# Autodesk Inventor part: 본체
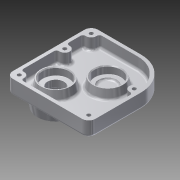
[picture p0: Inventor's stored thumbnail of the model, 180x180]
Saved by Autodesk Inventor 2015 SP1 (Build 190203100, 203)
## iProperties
Created: 2015-11
Part Number: 본체
Material: 알루미늄 6061
Document SubType Name: Modeling
Designer: moonsoo
Density: 2.7 g/cm^3
Appearance: 알루미늄 - 평지
Mass: 246.668 g
Surface Area: 389.43 cm^2
Volume: 91.3586 cm^3
Author: moonsoo
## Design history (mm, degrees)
sketch "스케치1"
  geometry: L1 (-42, 51.5)-(10, 51.5); L2 (50, 11.5)-(50, -43.5); L3 (42, -51.5)-(-42, -51.5); L4 (-50, -43.5)-(-50, 43.5); L5 (-50, 51.5)-(50, -51.5); L6 (50, 51.5)-(-50, -51.5); L7 (10, 47.5)-(-33.056, 47.5); L8 (-33.056, -47.5)-(33.056, -47.5); L9 (42, -43.5)-(42, 11.5); L10 (46, -34.556)-(46, 2.556); L11 (42, 11.5)-(-42, 11.5); L12 (-46, 34.556)-(-46, 20.444); L13 (-46, 2.556)-(-46, -34.556); L14 (-42, 43.5)-(-42, 11.5); A1 r 40 centre (10, 11.5) between (50, 11.5) and (10, 51.5); A2 r 8 centre (-42, 43.5) between (-42, 51.5) and (-50, 43.5); A3 r 8 centre (-42, -43.5) between (-50, -43.5) and (-42, -51.5); A4 r 8 centre (42, -43.5) between (42, -51.5) and (50, -43.5); A5 r 36 centre (10, 11.5) between (44.636, 21.314) and (10, 47.5); A6 r 6 centre (-42, 43.5) between (-42.667, 37.537) and (-36.037, 44.167); A7 r 3 centre (-33.056, 44.5) between (-33.056, 47.5) and (-36.037, 44.167); A8 r 3 centre (-43, 34.556) between (-42.667, 37.537) and (-46, 34.556); A9 r 6 centre (42, -43.5) between (42.667, -37.537) and (36.037, -44.167); A10 r 3 centre (43, -34.556) between (42.667, -37.537) and (46, -34.556); A11 r 3 centre (33.056, -44.5) between (33.056, -47.5) and (36.037, -44.167); A12 r 6 centre (42, 11.5) between (41.833, 17.498) and (42.667, 5.537); A13 r 3 centre (41.75, 20.497) between (41.833, 17.498) and (44.636, 21.314); A14 r 3 centre (43, 2.556) between (46, 2.556) and (42.667, 5.537); A15 r 6 centre (-42, 11.5) between (-42.667, 5.537) and (-42.667, 17.463); A16 r 3 centre (-43, 20.444) between (-46, 20.444) and (-42.667, 17.463); A17 r 3 centre (-43, 2.556) between (-42.667, 5.537) and (-46, 2.556); A18 r 6 centre (-42, -43.5) between (-36.037, -44.167) and (-42.667, -37.537); A19 r 3 centre (-43, -34.556) between (-46, -34.556) and (-42.667, -37.537); A20 r 3 centre (-33.056, -44.5) between (-36.037, -44.167) and (-33.056, -47.5); 10 further points
  constraints: 49 point on circle, 29 end point, 29 tangent, 20 centre point, 15 point on line, 7 equal radius, 5 coincident, 5 parallel, 5 perpendicular, 2 midpoint, 1 horizontal
  dimensions: "d0" = 100 distance of L5.end L6.end; "d1" = 103 distance of L6.start L5.end; "d2" = 40 radius of A1; "d3" = 8 radius of A2; "d4" = 4 distance between parallel lines of L7 L1; "d6" = 6 radius of A6; "d7" = 3 radius of A7; "d8" = 6 radius of A9; "d9" = 3 radius of A10; "d11" = 6 radius of A12; "d12" = 3 radius of A13; "d13" = 6 radius of A15; "d14" = 3 radius of A16; "d15" = 6 radius of A18; "d16" = 3 radius of A19; "d17" = 63 distance from line of L11.end L3; "d18" = 84 distance from line of A2.centre L9; "d19" = 4 distance between parallel lines of L2 L10; "d20" = 4 distance between parallel lines of L3 L8; "d21" = 4 distance between parallel lines of L13 L4; "d22" = 3 radius of A17 (derived)
extrude "돌출1" new body sketch "스케치1" distance "d23" = 18; taper "d24" = 0 deg
extrude "돌출2" join sketch "스케치1" distance "d25" = 4; taper "d26" = 0 deg
sketch "스케치2"
  geometry: A1 r 8 centre (-42, -43.5) between (-50, -43.5) and (-42, -51.5) reference; A2 r 8 centre (42, -43.5) between (42, -51.5) and (50, -43.5) reference; A3 r 6 centre (42, 43.5) between (36.037, 44.167) and (42.667, 37.537) reference; 6 further points
  constraints: 3 coincident
hole "구멍2" sketch "스케치2" at (-42, -43.5), (42, 11.5), (42, 43.5), (42, -43.5), (-42, 11.5) diameter "d34" = 4.5; stored, may be unused: countersink angle "d38" = 90 deg, drill point angle "d40" = 118 deg; dims "d35" = 6, "d36" = 8, "d37" = 4.4, "d39" = 8
sketch "스케치3"
  geometry: L1 (-42, -51.5)-(42, -51.5) reference; L2 (-42, 11.5)-(42, 11.5); L3 (-50, 43.5)-(-50, -43.5) reference; L4 (10, 43.5)-(10, -43.5); C1 r 2.25 at (42, -43.5) reference; C2 r 20 at (10, 11.5); A1 r 36 centre (10, 11.5) between (44.636, 21.314) and (10, 47.5) reference; 1 further point
  constraints: 4 end point, 2 parallel, 1 centre point, 1 coincident
  dimensions: "d42" = 63 distance between parallel lines of L1 L2; "d43" = 60 distance between parallel lines of L3 L4; "d44" = 40 diameter of C2
extrude "돌출3" join sketch "스케치3" distance "d45" = 11; taper "d46" = -10 deg
hole "구멍3" diameter "d49" = 22; stored, may be unused: countersink angle "d53" = 90 deg, drill point angle "d55" = 0 deg; dims "d50" = 6, "d51" = 32, "d52" = 9, "d54" = 11, "d60" = 10, "d61" = 10
chamfer "모따기1" distance "d56" = 1; stored, may be unused: second distance "d57" = 2, angle "d58" = 45 deg
fillet "모깎기1" dims "d59" = 3
fillet "모깎기2" dims "d62" = 0.3
sketch "스케치4"
  geometry: L1 (-42, -51.5)-(42, -51.5) reference; L2 (-50, -21.5)-(42, -21.5); L3 (-50, 43.5)-(-50, -43.5) reference; L4 (-33.056, 47.5)-(10, 47.5) reference; L5 (-46, 20.444)-(-46, 34.556) reference; L6 (-46, -34.556)-(-46, 2.556) reference; L7 (33.056, -47.5)-(-33.056, -47.5) reference; L8 (46, 2.556)-(46, -34.556) reference; L9 (-20, 43.5)-(-20, -43.5); C1 r 20 at (10, 11.5) reference; C2 r 20 at (-20, -21.5); A1 r 3 centre (-33.056, 44.5) between (-33.056, 47.5) and (-36.037, 44.167) reference; A2 r 6 centre (-42, 43.5) between (-42.667, 37.537) and (-36.037, 44.167) reference; A3 r 3 centre (-43, 34.556) between (-42.667, 37.537) and (-46, 34.556) reference; A4 r 3 centre (-43, 20.444) between (-46, 20.444) and (-42.667, 17.463) reference; A5 r 6 centre (-42, 11.5) between (-42.667, 5.537) and (-42.667, 17.463) reference; A6 r 3 centre (-43, 2.556) between (-42.667, 5.537) and (-46, 2.556) reference; A7 r 3 centre (-43, -34.556) between (-46, -34.556) and (-42.667, -37.537) reference; A8 r 6 centre (-42, -43.5) between (-36.037, -44.167) and (-42.667, -37.537) reference; A9 r 3 centre (-33.056, -44.5) between (-36.037, -44.167) and (-33.056, -47.5) reference; A10 r 3 centre (33.056, -44.5) between (33.056, -47.5) and (36.037, -44.167) reference; A11 r 6 centre (42, -43.5) between (42.667, -37.537) and (36.037, -44.167) reference; A12 r 3 centre (43, -34.556) between (42.667, -37.537) and (46, -34.556) reference; A13 r 3 centre (43, 2.556) between (46, 2.556) and (42.667, 5.537) reference; A14 r 6 centre (42, 11.5) between (41.833, 17.498) and (42.667, 5.537) reference; A15 r 3 centre (41.75, 20.497) between (41.833, 17.498) and (44.636, 21.314) reference; A16 r 36 centre (10, 11.5) between (44.636, 21.314) and (10, 47.5) reference; 1 further point
  constraints: 4 end point, 3 point on line, 2 parallel, 1 centre point
  dimensions: "d63" = 30 distance between parallel lines of L1 L2; "d64" = 30 distance between parallel lines of L3 L9; "d65" = 40 diameter of C2
extrude "돌출4" join sketch "스케치4" distance "d66" = 11; taper "d67" = -10 deg
fillet "모깎기3" dims "d78" = 3
fillet "모깎기4" dims "d79" = 3
sketch "스케치9"
  geometry: L1 (50, -43.5)-(50, 43.5) reference; L2 (42, 51.5)-(-10, 51.5) reference; 2 further points
  constraints: 1 other
  dimensions: "d123" = 40 distance from line of point (10, 31.5) L1; "d124" = 20 distance from line of point (10, 31.5) L2
feature "엠보싱1" sketch "스케치9" dims "d125" = 0.5, "d126" = 0
fillet "모깎기10" dims "d127" = 3
sketch "스케치12"
  geometry: C1 r 19.563 at (20, -21.5) reference; C2 r 25 at (20, -21.5); 1 further point
  constraints: 1 centre point, 1 coincident
  dimensions: "d137" = 50 diameter of C2
extrude "돌출8" join sketch "스케치12" distance "d138" = 15; taper "d139" = -10 deg
fillet "모깎기11" dims "d140" = 3
hole "구멍8" diameter "d143" = 24; stored, may be unused: countersink angle "d147" = 90 deg, drill point angle "d149" = 0 deg; dims "d141" = 10, "d142" = 10, "d144" = 6, "d145" = 28, "d146" = 11, "d148" = 13
fillet "모깎기12" dims "d150" = 0.3
fillet "모깎기13" dims "d151" = 3
hole "구멍9" diameter "d154" = 20; stored, may be unused: countersink angle "d158" = 90 deg, drill point angle "d160" = 0 deg; dims "d152" = 10, "d153" = 10, "d155" = 6, "d156" = 32, "d157" = 9, "d159" = 13
fillet "모깎기14" dims "d161" = 0.3
chamfer "모따기5" distance "d162" = 1; stored, may be unused: second distance "d163" = 2, angle "d164" = 45 deg
chamfer "모따기6" distance "d165" = 1; stored, may be unused: second distance "d166" = 2, angle "d167" = 45 deg
sketch "스케치13" dims "d168" = 36
  geometry: 3 further points
  constraints: 1 horizontal alignment, 2 other
hole "구멍11" sketch "스케치13" at (-18, 0) diameter "d179" = 2.459; stored, may be unused: countersink angle "d183" = 90 deg, drill point angle "d185" = 118 deg; dims "d180" = 8, "d181" = 32, "d182" = 9, "d184" = 10
node "솔리드1"
pattern_circular "원형 패턴3" dims angle "d187" = 360 deg
node "투영된 루프1"
